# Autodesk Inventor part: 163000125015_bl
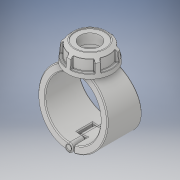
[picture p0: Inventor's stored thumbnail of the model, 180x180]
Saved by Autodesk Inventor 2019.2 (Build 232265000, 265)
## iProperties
Created: 2022-02
Part Number: 163000125015_bl
Material: Generic
Description: Plassadle Threaded 125x1 1/2''
Document SubType Name: Modeling
Designer: comp2
Density: 1 g/cm^3
Appearance: Default
Author: comp2
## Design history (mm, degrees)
derived "16300.ipt"
feature "Solid1::16300.ipt" dims "ScaleForDerivedMember" = 10
feature "Solid2::16300.ipt" dims "ScaleForDerivedMember" = 10
feature "Solid3::16300.ipt" dims "ScaleForDerivedMember" = 10
feature "Solid4::16300.ipt" dims "ScaleForDerivedMember" = 10
tag "TaggingFeature1"
body "Solid1"
body "Solid2"
body "Solid3"
body "Solid4"
other parameters: "d0" = 125 [user parameter], "d2" = 157 [user parameter], "d3" = 62.5 [user parameter], "d7" = 149.15 [user parameter], "d8" = 85 deg [user parameter], "d9" = 45 deg [user parameter], "d10" = 102 [user parameter], "d11" = 49 [user parameter], "d12" = 29.2495 [user parameter], "d13" = 42.84 [user parameter], "d14" = 67.2675 [user parameter], "d42" = 3.2 [user parameter], "d49" = 3.14 [user parameter], "d51" = 0 [user parameter], "d52" = 22.4 [user parameter], "d53" = 86.35 [user parameter], "d54" = 35 [user parameter], "d55" = 0 [user parameter], "d59" = 0 [user parameter], "d61" = 0 [user parameter], "d62" = 35 [user parameter], "d63" = 0 [user parameter], "d65" = 0 [user parameter], "d67" = 0 [user parameter], "d69" = 0 [user parameter], "d70" = 1 [user parameter], "d71" = 96 [user parameter], "d72" = 0 [user parameter], "d73" = 2 [user parameter], "d78" = 86.7 [user parameter], "d79" = 5.1 [user parameter], "d80" = 60 deg [user parameter], "d81" = 5.1 [user parameter], "d84" = 0 [user parameter], "d85" = 1 [user parameter], "d87" = 360 deg [user parameter], "d122" = 49 [user parameter], "d124" = 42.80128 [user parameter], "d125" = 2.08925 [user parameter], "d127" = 198 [user parameter], "d129" = 44.845 [user parameter], "d130" = 38.11825 [user parameter], "d131" = 31.85 [user parameter], "d132" = 45 deg [user parameter], "d133" = 22.295 [user parameter], "d134" = 22.4225 [user parameter], "d136" = 0 [user parameter], "d138" = 0 [user parameter], "d" = 125 [user parameter], "d1" = 25 [user parameter], "B" = 157 [user parameter], "E_" = 54 [user parameter], "E1" = 102 [user parameter], "H1" = 198 [user parameter], "H2" = 49 [user parameter], "H3" = 78 [user parameter], "H_costum" = 49 [user parameter], "Rp" = 44.845 [user parameter], "d128" = 41.785 [user parameter]
